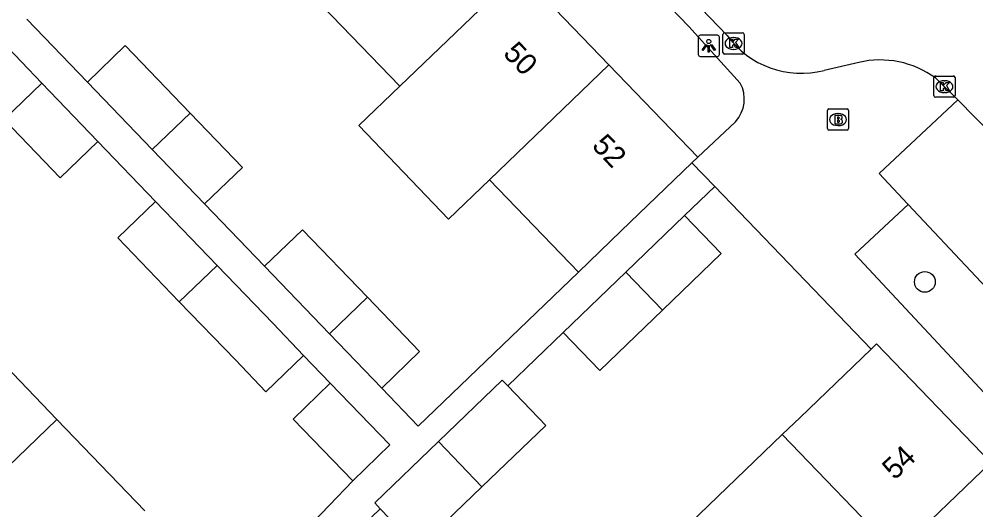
# Model space of a CAD drawing. Extents: x 159040 to 160094, y 381214 to 382518.
# Drawn here: x 159553.25 to 159598.33, y 382077.42 to 382100.53 of the extents above; entities that cross this region are included whole.
import ezdxf

# ---------------------------------------------------------------- set-up
doc = ezdxf.new("R2010")
doc.units = 0
for name, color, linetype in [('IMGEO_Boom', 7, 'Continuous'), ('IMGEO_Brandkraan', 7, 'Continuous'), ('IMGEO_Kolk', 7, 'Continuous'), ('IMGEO_Lichtpunt', 7, 'Continuous'), ('IMGEO_Pand', 7, 'Continuous'), ('IMGEO_Pand_nummerreeks', 7, 'Continuous'), ('IMGEO_Parkeervlak_open', 7, 'Continuous'), ('IMGEO_Rijbaan_lokaal_open', 7, 'Continuous'), ('IMGEO_Voetpad_open', 7, 'Continuous')]:
    doc.layers.add(name, color=color, linetype=linetype)

msp = doc.modelspace()

# ---------------------------------------------------------------- linework, layer by layer
at = {"layer": 'IMGEO_Boom'}
msp.add_circle((159595.924, 382088.15), 0.489, dxfattribs=at)
at = {"layer": 'IMGEO_Brandkraan'}
for p, q in [((159591.406, 382096.296), (159592.258, 382096.296)), ((159591.331, 382095.37), (159591.331, 382096.222)), ((159591.819, 382096.076), (159591.844, 382096.076)), ((159592.332, 382096.222), (159592.332, 382095.37)), ((159591.842, 382095.516), (159591.817, 382095.516)), ((159592.258, 382095.296), (159591.406, 382095.296))]:
    msp.add_line(p, q, dxfattribs=at)
for points in [[(159591.406, 382096.296), (159592.258, 382096.296)], [(159591.331, 382095.37), (159591.331, 382096.222)], [(159591.679, 382095.996), (159591.679, 382095.596), (159591.892, 382095.596)], [(159591.91, 382095.996), (159591.679, 382095.996)], [(159591.858, 382095.915), (159591.804, 382095.915), (159591.804, 382095.839)], [(159591.804, 382095.839), (159591.857, 382095.839)], [(159592.332, 382096.222), (159592.332, 382095.37)], [(159591.866, 382095.763), (159591.804, 382095.763), (159591.804, 382095.682)], [(159591.804, 382095.682), (159591.866, 382095.682)], [(159592.258, 382095.296), (159591.406, 382095.296)]]:
    msp.add_lwpolyline(points, dxfattribs=at)
for centre, radius, start, end in [((159591.408, 382096.22), 0.0765, 91.552, 178.448), ((159591.408, 382096.22), 0.0765, 91.552, 178.448), ((159592.256, 382096.22), 0.0765, 1.552, 88.448), ((159592.256, 382096.22), 0.0765, 1.552, 88.448), ((159591.859, 382095.877), 0.0379, 267.8285, 90.9355), ((159591.914, 382095.851), 0.145, 59.4692, 91.5367), ((159591.939, 382095.898), 0.0922, 285.5137, 58.1501), ((159591.408, 382095.372), 0.0765, 181.552, 268.448), ((159591.408, 382095.372), 0.0765, 181.552, 268.448), ((159591.867, 382095.722), 0.0404, 269.8759, 90.5077), ((159591.898, 382095.847), 0.251, 268.6676, 293.5347), ((159591.944, 382095.706), 0.105, 301.3115, 78.989), ((159592.256, 382095.372), 0.0765, 271.552, 358.448), ((159592.256, 382095.372), 0.0765, 271.552, 358.448)]:
    msp.add_arc(centre, radius, start, end, dxfattribs=at)
for centre, major_axis, ratio, start_param, end_param in [((159591.818, 382095.796), (-0.387, 0.002), 0.722429, 4.712389, 7.853982), ((159591.843, 382095.796), (-0.39, 0.002), 0.717154, 1.570796, 4.712389)]:
    msp.add_ellipse(centre, major_axis=major_axis, ratio=ratio, start_param=start_param, end_param=end_param, dxfattribs=at)
at = {"layer": 'IMGEO_Kolk'}
for p, q in [((159586.485, 382099.884), (159587.337, 382099.884)), ((159586.41, 382098.958), (159586.41, 382099.81)), ((159586.898, 382099.664), (159586.923, 382099.664)), ((159587.411, 382099.81), (159587.411, 382098.958)), ((159586.921, 382099.104), (159586.896, 382099.104)), ((159587.337, 382098.884), (159586.485, 382098.884)), ((159596.348, 382096.923), (159596.348, 382097.775)), ((159596.423, 382097.849), (159597.275, 382097.849)), ((159596.836, 382097.629), (159596.861, 382097.629)), ((159597.349, 382097.775), (159597.349, 382096.923)), ((159597.275, 382096.849), (159596.423, 382096.849)), ((159596.859, 382097.069), (159596.834, 382097.069))]:
    msp.add_line(p, q, dxfattribs=at)
for points in [[(159586.485, 382099.884), (159587.337, 382099.884)], [(159586.41, 382098.958), (159586.41, 382099.81)], [(159586.731, 382099.584), (159586.854, 382099.584), (159586.854, 382099.433), (159586.984, 382099.584), (159587.148, 382099.584), (159587.002, 382099.433), (159587.155, 382099.184), (159587.003, 382099.184), (159586.918, 382099.348), (159586.854, 382099.281), (159586.854, 382099.184), (159586.731, 382099.184), (159586.731, 382099.584)], [(159587.411, 382099.81), (159587.411, 382098.958)], [(159587.337, 382098.884), (159586.485, 382098.884)], [(159596.348, 382096.923), (159596.348, 382097.775)], [(159596.423, 382097.849), (159597.275, 382097.849)], [(159597.349, 382097.775), (159597.349, 382096.923)], [(159596.669, 382097.549), (159596.792, 382097.549), (159596.792, 382097.398), (159596.922, 382097.549), (159597.086, 382097.549), (159596.94, 382097.398), (159597.093, 382097.149), (159596.941, 382097.149), (159596.856, 382097.313), (159596.792, 382097.246), (159596.792, 382097.149), (159596.669, 382097.149), (159596.669, 382097.549)], [(159597.275, 382096.849), (159596.423, 382096.849)]]:
    msp.add_lwpolyline(points, dxfattribs=at)
for centre, start, end in [((159586.487, 382099.808), 91.552, 178.448), ((159586.487, 382099.808), 91.552, 178.448), ((159587.335, 382099.808), 1.552, 88.448), ((159587.335, 382099.808), 1.552, 88.448), ((159586.487, 382098.96), 181.552, 268.448), ((159586.487, 382098.96), 181.552, 268.448), ((159587.335, 382098.96), 271.552, 358.448), ((159587.335, 382098.96), 271.552, 358.448), ((159596.425, 382097.773), 91.552, 178.448), ((159596.425, 382097.773), 91.552, 178.448), ((159597.273, 382097.773), 1.552, 88.448), ((159597.273, 382097.773), 1.552, 88.448), ((159596.425, 382096.925), 181.552, 268.448), ((159596.425, 382096.925), 181.552, 268.448), ((159597.273, 382096.925), 271.552, 358.448), ((159597.273, 382096.925), 271.552, 358.448)]:
    msp.add_arc(centre, 0.0765, start, end, dxfattribs=at)
for centre, major_axis, ratio, start_param, end_param in [((159586.897, 382099.384), (-0.387, 0.002), 0.722429, 4.712389, 7.853982), ((159586.922, 382099.384), (-0.39, 0.002), 0.717154, 1.570796, 4.712389), ((159596.835, 382097.349), (-0.387, 0.002), 0.722429, 4.712389, 7.853982), ((159596.86, 382097.349), (-0.39, 0.002), 0.717154, 1.570796, 4.712389)]:
    msp.add_ellipse(centre, major_axis=major_axis, ratio=ratio, start_param=start_param, end_param=end_param, dxfattribs=at)
at = {"layer": 'IMGEO_Lichtpunt'}
for p, q in [((159585.245, 382099.676), (159585.245, 382098.869)), ((159585.245, 382099.676), (159585.245, 382098.869)), ((159586.147, 382099.771), (159585.339, 382099.771)), ((159586.147, 382099.771), (159585.339, 382099.771)), ((159586.241, 382098.869), (159586.241, 382099.676)), ((159586.241, 382098.869), (159586.241, 382099.676)), ((159585.339, 382098.775), (159586.147, 382098.775)), ((159585.339, 382098.775), (159586.147, 382098.775))]:
    msp.add_line(p, q, dxfattribs=at)
for points in [[(159585.619, 382099.34), (159585.658, 382099.312), (159585.47, 382099.05), (159585.432, 382099.077), (159585.619, 382099.34)], [(159585.721, 382099.292), (159585.768, 382099.292), (159585.768, 382098.97), (159585.721, 382098.97), (159585.721, 382099.292)], [(159585.831, 382099.312), (159585.869, 382099.339), (159586.056, 382099.077), (159586.017, 382099.049), (159585.831, 382099.312)]]:
    msp.add_lwpolyline(points, dxfattribs=at)
msp.add_circle((159585.744, 382099.474), 0.0994, dxfattribs=at)
for centre, start, end in [((159585.339, 382099.676), 90, 180), ((159585.339, 382099.676), 90, 180), ((159586.147, 382099.676), 0, 90), ((159586.147, 382099.676), 0, 90), ((159585.339, 382098.869), 180, 270), ((159585.339, 382098.869), 180, 270), ((159586.147, 382098.869), 270, 0), ((159586.147, 382098.869), 270, 360)]:
    msp.add_arc(centre, 0.0946, start, end, dxfattribs=at)
at = {"layer": 'IMGEO_Pand'}
for points in [[(159576.808, 382102.772), (159571.183, 382097.363)], [(159581.038, 382098.376), (159576.808, 382102.772)], [(159571.183, 382097.363), (159567.067, 382101.641)], [(159551.423, 382100.524), (159554.323, 382097.51)], [(159556.467, 382097.564), (159558.253, 382099.282), (159561.31, 382096.104)], [(159575.413, 382092.966), (159581.038, 382098.376)], [(159581.038, 382098.376), (159585.224, 382094.024)], [(159552.544, 382095.798), (159554.323, 382097.51)], [(159554.323, 382097.51), (159556.963, 382094.765)], [(159559.524, 382094.386), (159556.467, 382097.564)], [(159575.413, 382092.966), (159573.488, 382091.114), (159569.258, 382095.511), (159571.183, 382097.363)], [(159559.524, 382094.386), (159561.31, 382096.104)], [(159561.31, 382096.104), (159563.773, 382093.543), (159561.988, 382091.825)], [(159556.963, 382094.765), (159555.184, 382093.054), (159552.544, 382095.798)], [(159561.988, 382091.825), (159559.524, 382094.386)], [(159585.224, 382094.024), (159584.952, 382093.763)], [(159584.952, 382093.763), (159581.621, 382090.559), (159579.599, 382088.614)], [(159579.599, 382088.614), (159575.413, 382092.966)], [(159560.797, 382087.219), (159557.897, 382090.234), (159559.676, 382091.945)], [(159559.676, 382091.945), (159562.576, 382088.931)], [(159581.838, 382088.617), (159584.602, 382091.276)], [(159584.602, 382091.276), (159586.326, 382089.483), (159583.562, 382086.825)], [(159564.813, 382088.889), (159566.599, 382090.607), (159569.656, 382087.429)], [(159562.576, 382088.931), (159560.797, 382087.219)], [(159566.651, 382084.684), (159565.216, 382086.186), (159562.576, 382088.931)], [(159567.87, 382085.711), (159564.813, 382088.889)], [(159578.881, 382085.774), (159581.838, 382088.617)], [(159581.838, 382088.617), (159583.562, 382086.825)], [(159567.87, 382085.711), (159569.656, 382087.429)], [(159569.656, 382087.429), (159572.119, 382084.868), (159570.334, 382083.15)], [(159560.797, 382087.219), (159563.437, 382084.475), (159564.877, 382082.978), (159566.651, 382084.684)], [(159583.562, 382086.825), (159580.605, 382083.981), (159578.881, 382085.774)], [(159550.858, 382085.999), (159555.026, 382081.666)], [(159570.334, 382083.15), (159567.87, 382085.711)], [(159593.388, 382084.983), (159593.651, 382085.236), (159599.031, 382079.644)], [(159589.206, 382080.96), (159590.048, 382081.77), (159593.388, 382084.983)], [(159568.978, 382078.786), (159566.157, 382081.688), (159567.898, 382083.38)], [(159567.898, 382083.38), (159570.719, 382080.478), (159568.978, 382078.786)], [(159576.271, 382083.251), (159576.01, 382083.522), (159573.007, 382080.631)], [(159575.056, 382078.501), (159578.06, 382081.392), (159576.271, 382083.251)], [(159549.462, 382076.312), (159555.026, 382081.666)], [(159555.026, 382081.666), (159559.169, 382077.362)], [(159584.868, 382076.786), (159589.206, 382080.96)], [(159594.587, 382075.368), (159589.206, 382080.96)], [(159573.007, 382080.631), (159570.003, 382077.741), (159570.264, 382077.469)], [(159575.056, 382078.501), (159573.007, 382080.631)], [(159599.031, 382079.644), (159594.587, 382075.368)], [(159570.264, 382077.469), (159572.053, 382075.611), (159575.056, 382078.501)]]:
    msp.add_lwpolyline(points, dxfattribs=at)
at = {"layer": 'IMGEO_Parkeervlak_open'}
msp.add_lwpolyline([(159595.131, 382091.799), (159602.988, 382083.451), (159603.007, 382083.43)], dxfattribs=at)
at = {"layer": 'IMGEO_Rijbaan_lokaal_open'}
for points in [[(159586.605, 382099.764), (159574.738, 382112.092), (159560.721, 382126.678)], [(159592.818, 382098.491), (159591.177, 382098.11)], [(159597.484, 382096.733), (159596.425, 382097.759)], [(159610.676, 382083.287), (159597.484, 382096.733)]]:
    msp.add_lwpolyline(points, dxfattribs=at)
for centre, radius, start, end in [((159590.104, 382102.291), 4.316, 215.8328, 284.3903), ((159593.815, 382094.151), 4.453, 54.1199, 102.9367)]:
    msp.add_arc(centre, radius, start, end, dxfattribs=at)
at = {"layer": 'IMGEO_Voetpad_open'}
for points in [[(159559.521, 382126.397), (159584.804, 382100.173), (159587.227, 382097.515)], [(159556.467, 382097.564), (159553.614, 382100.53)], [(159595.131, 382091.799), (159595.104, 382091.828), (159593.765, 382093.251), (159597.484, 382096.733)], [(159587.009, 382095.696), (159585.224, 382094.024)], [(159556.963, 382094.765), (159559.676, 382091.945)], [(159586.026, 382092.646), (159584.952, 382093.763)], [(159584.602, 382091.276), (159586.026, 382092.646)], [(159593.388, 382084.983), (159586.026, 382092.646)], [(159564.813, 382088.889), (159561.988, 382091.825)], [(159603.007, 382083.43), (159600.462, 382081.054), (159592.623, 382089.456), (159595.131, 382091.799)], [(159579.599, 382088.614), (159572.057, 382081.359), (159570.334, 382083.15)], [(159576.271, 382083.251), (159578.881, 382085.774)], [(159566.651, 382084.684), (159567.898, 382083.38)], [(159568.978, 382078.786), (159563.393, 382072.971)], [(159567.401, 382074.714), (159570.264, 382077.469)]]:
    msp.add_lwpolyline(points, dxfattribs=at)
msp.add_arc((159585.81, 382096.762), 1.605, 318.3636, 27.9683, dxfattribs=at)

# ---------------------------------------------------------------- texts
at = {"layer": 'IMGEO_Pand_nummerreeks'}
for s, rotation, p in [('50', 313.8884, (159576.01, 382098.871)), ('52', 313.8895, (159580.192, 382094.524)), ('54', 43.8962, (159594.504, 382078.785))]:
    msp.add_text(s, height=1, rotation=rotation, dxfattribs=at).set_placement(p)

doc.saveas('drawing.dxf')
